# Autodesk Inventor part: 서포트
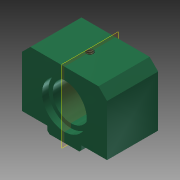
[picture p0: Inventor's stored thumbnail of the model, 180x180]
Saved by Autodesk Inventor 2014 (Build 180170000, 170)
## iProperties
Created: 2019-04
Part Number: 서포트
Material: 알루미늄 6061
Document SubType Name: Modeling
Designer: mduedu
Density: 1 g/cm^3
Appearance: Smooth - Dark Sea Green
Author: mduedu
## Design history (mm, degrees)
sketch "스케치1"
  geometry: L1 (3, 20)-(31, 20); L2 (31, 20)-(31, -20); L3 (31, -20)-(3, -20); L4 (0, -8)-(0, 8); L5 (0, 8)-(3, 8); L6 (3, 8)-(3, 20); L7 (0, 0)-(31, 0); L8 (0, -8)-(3, -8); L9 (3, -8)-(3, -20); 1 further point
  constraints: 18 end point, 3 symmetric about line, 2 horizontal, 2 midpoint, 2 parallel, 2 perpendicular, 1 coincident
  dimensions: "d3" = 31 distance between parallel lines of L4 L2; "d5" = 16 distance of L4.start L4.end; "d6" = 40 distance between parallel lines of L3 L1; "d7" = 3 distance between parallel lines of L4 L9
extrude "돌출1" new body sketch "스케치1" distance "d8" = 24; taper "d9" = 0 deg
chamfer "모따기1" distance "d10" = 4; stored, may be unused: second distance "d11" = 2, angle "d12" = 45 deg
chamfer "모따기2" distance "d13" = 1; stored, may be unused: second distance "d14" = 2, angle "d15" = 45 deg
sketch "스케치2"
  geometry: L1 (7, 0)-(-7, 0) reference; L2 (20, 3)-(8, 3) reference; 3 further points
  constraints: 1 midpoint, 1 vertical alignment
  dimensions: "d24" = 12 distance from line of point (0, 15) L2
hole "구멍1" sketch "스케치2" at (0, 15) diameter "d17" = 17; stored, may be unused: countersink angle "d21" = 90 deg, drill point angle "d23" = 118 deg; dims "d18" = 6, "d19" = 21, "d20" = 3, "d22" = 8
sketch "스케치3"
  geometry: L1 (0, 32)-(0, 0) reference; 3 further points
  constraints: 1 horizontal alignment, 1 midpoint
  dimensions: "d25" = 12 distance from line of point (12, 16) L1
hole "구멍2" sketch "스케치3" at (12, 16) diameter "d26" = 3.242; stored, may be unused: countersink angle "d30" = 90 deg, drill point angle "d32" = 118 deg; dims "d27" = 6, "d28" = 21, "d29" = 3, "d31" = 8
sketch "스케치4"
  geometry: L1 (0, -8)-(24, -8); L2 (24, 0.5)-(24, -16.5) reference; L3 (0, -28)-(0, -24) reference; 4 further points
  constraints: 2 end point, 2 symmetric about line, 1 horizontal, 1 horizontal alignment, 1 midpoint
  dimensions: "d33" = 6 distance from line of point (6, -22) L3; "d34" = 12 distance of point (18, -22) point (6, -22); "d35" = 28 distance of point (6, 6) point (6, -22); "d36" = 14 distance from line of point (6, -22) L1 (derived)
hole "구멍3" sketch "스케치4" at (6, -22), (18, -22), (18, 6), (6, 6) diameter "d37" = 3.242; stored, may be unused: countersink angle "d41" = 90 deg, drill point angle "d43" = 118 deg; dims "d38" = 9, "d39" = 21, "d40" = 3, "d42" = 11
workplane "Work Plane1"
node "솔리드1"
